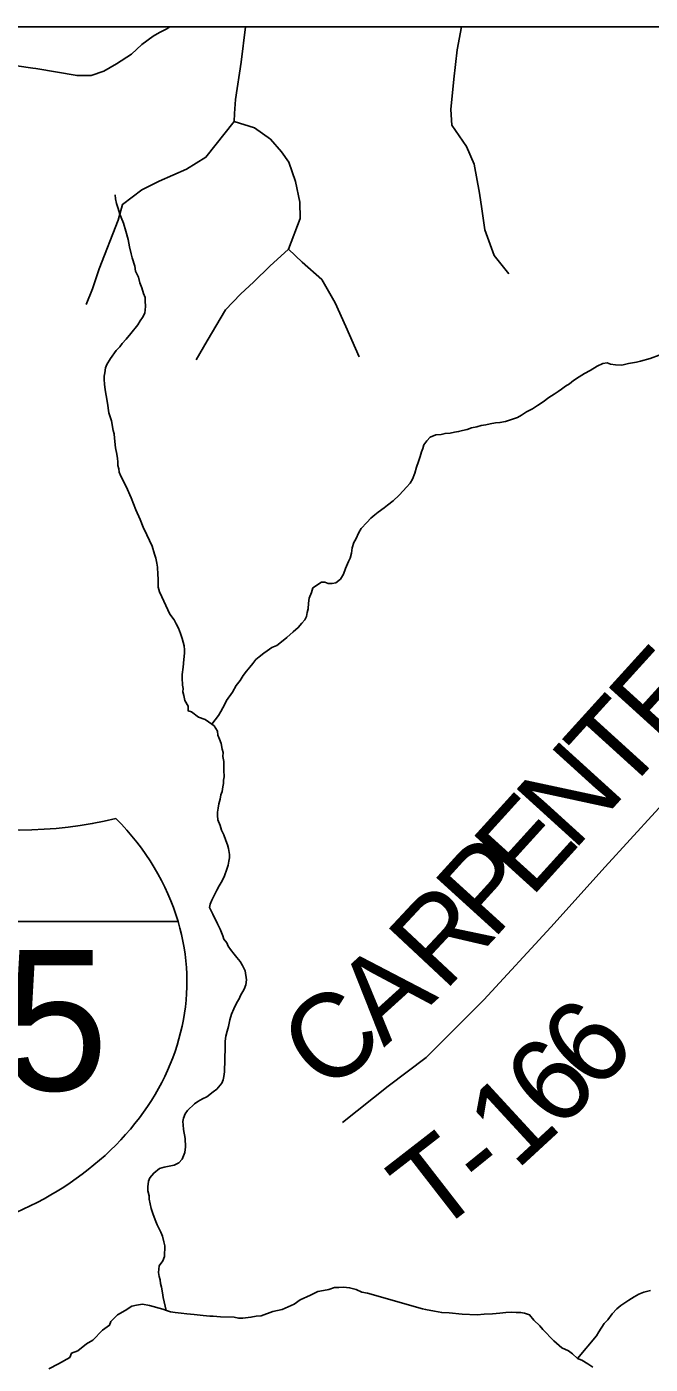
# Model space of a CAD drawing. Extents: x 0 to 34, y 0 to 22.
# Drawn here: x 7.1167 to 7.327, y 20.4487 to 20.9 of the extents above; entities that cross this region are included whole.
import ezdxf

# ---------------------------------------------------------------- set-up
doc = ezdxf.new("R2010")
doc.units = 0
for name, color, linetype in [('GM_X_Corporation', 7, 'Continuous'), ('GM_X_Interstate_Shield', 7, 'Continuous'), ('GM_X_Minor_River', 7, 'Continuous'), ('GM_X_Township_Road', 7, 'Continuous'), ('GM_X_Township_Road_Text', 7, 'Continuous'), ('SH_Cut_Line', 7, 'Continuous'), ('SH_Data', 7, 'Continuous')]:
    doc.layers.add(name, color=color, linetype=linetype)

msp = doc.modelspace()

# ---------------------------------------------------------------- linework, layer by layer
at = {"layer": 'GM_X_Corporation'}
msp.add_lwpolyline([(8.26616, 20.9), (5.67696, 20.9)], dxfattribs=at)
at = {"layer": 'GM_X_Interstate_Shield'}
msp.add_line((7.16774, 20.59808), (6.99605, 20.59808), dxfattribs=at)
msp.add_line((7.16774, 20.59808), (6.99605, 20.59808), dxfattribs=at)
for centre, start_param, end_param in [((7.11432, 20.71775), 4.415841, 5.008937), ((7.0597, 20.57779), 0.230566, 0.669003), ((7.0597, 20.57779), 4.913747, 6.513751)]:
    msp.add_ellipse(centre, major_axis=(0.11097, 0), ratio=0.8, start_param=start_param, end_param=end_param, dxfattribs=at)
at = {"layer": 'GM_X_Minor_River'}
for points in [[(7.15307, 20.8192), (7.15219, 20.82206), (7.15185, 20.8234), (7.15134, 20.82569), (7.15083, 20.82817), (7.15014, 20.83103), (7.14926, 20.83371), (7.14855, 20.83563), (7.14801, 20.83678), (7.14749, 20.83869), (7.14696, 20.84041), (7.14662, 20.84194), (7.14646, 20.84327)], [(7.18105, 20.63504), (7.18127, 20.63636), (7.1815, 20.63787), (7.18192, 20.63938), (7.18215, 20.64089), (7.18256, 20.64202), (7.18278, 20.64353), (7.183, 20.64466), (7.18303, 20.6458), (7.18325, 20.64693), (7.18312, 20.64921), (7.18319, 20.65206), (7.18285, 20.65377), (7.18289, 20.6551), (7.18254, 20.65625), (7.18221, 20.65815), (7.18168, 20.65968), (7.18114, 20.66102), (7.18098, 20.66236), (7.17989, 20.66409), (7.17802, 20.66547), (7.17691, 20.66626), (7.17465, 20.66707), (7.17222, 20.66884), (7.17109, 20.66925), (7.17113, 20.67077), (7.17004, 20.6727), (7.16971, 20.67441), (7.16936, 20.67556), (7.16938, 20.6767), (7.16922, 20.67784), (7.1691, 20.68031), (7.16913, 20.68144), (7.16938, 20.6839), (7.16963, 20.68655), (7.16988, 20.68863), (7.16991, 20.68977), (7.16975, 20.6911), (7.16905, 20.69359), (7.16853, 20.69531), (7.16781, 20.69703), (7.16709, 20.69857), (7.16637, 20.69992), (7.1649, 20.70185), (7.16219, 20.70761), (7.16148, 20.70934), (7.16095, 20.71087), (7.16102, 20.71371), (7.16087, 20.71524), (7.16074, 20.7177), (7.16059, 20.71904), (7.16025, 20.72075), (7.15971, 20.72209), (7.15902, 20.72477), (7.15722, 20.72861), (7.15596, 20.73111), (7.15488, 20.73379), (7.15345, 20.73705), (7.15184, 20.74108), (7.15023, 20.74491), (7.14842, 20.74838), (7.14788, 20.74972), (7.14772, 20.75086), (7.14737, 20.75201), (7.1474, 20.75315), (7.14724, 20.75429), (7.14709, 20.75581), (7.14657, 20.75791), (7.14627, 20.76114), (7.14612, 20.76266), (7.14577, 20.76381), (7.14529, 20.76705), (7.1444, 20.76973), (7.14392, 20.77296), (7.14341, 20.77563), (7.14308, 20.77754), (7.14294, 20.77944), (7.14279, 20.78096), (7.14282, 20.7821), (7.14304, 20.78323), (7.14327, 20.78493), (7.14368, 20.78606), (7.14487, 20.78811), (7.14684, 20.79072), (7.14801, 20.79201), (7.1488, 20.79313), (7.15016, 20.79461), (7.15173, 20.79647), (7.15409, 20.79944), (7.15488, 20.80075), (7.15567, 20.80187), (7.15646, 20.80336), (7.15671, 20.80563), (7.15657, 20.80753), (7.1566, 20.80867), (7.15606, 20.81001), (7.15554, 20.81192), (7.15483, 20.81365), (7.15431, 20.81556), (7.1534, 20.81748), (7.15307, 20.8192)], [(7.3031, 20.78188), (7.30483, 20.78298), (7.30676, 20.78406), (7.30908, 20.78552), (7.311, 20.78642), (7.31252, 20.78657), (7.31365, 20.78616), (7.31535, 20.78593), (7.31744, 20.78587), (7.31973, 20.78638), (7.32241, 20.78688), (7.32374, 20.78722), (7.32699, 20.78809), (7.33006, 20.78915)], [(7.17911, 20.66466), (7.18131, 20.66766), (7.1821, 20.66897), (7.18349, 20.67139), (7.1841, 20.67271), (7.18607, 20.6755), (7.18726, 20.67775), (7.18863, 20.67942), (7.18963, 20.6811), (7.1908, 20.68258), (7.19198, 20.68388), (7.19296, 20.68518), (7.19394, 20.68649), (7.1951, 20.6874), (7.19666, 20.68869), (7.19781, 20.68942), (7.19936, 20.69052), (7.20109, 20.69123), (7.20264, 20.69252), (7.20439, 20.69399), (7.20652, 20.69583), (7.20827, 20.6973), (7.20945, 20.69879), (7.21043, 20.6999), (7.21102, 20.70102), (7.21125, 20.70234), (7.21166, 20.70366), (7.21171, 20.70556), (7.21194, 20.70726), (7.21275, 20.70913), (7.21317, 20.71064), (7.21607, 20.71265), (7.21721, 20.71262), (7.21833, 20.71221), (7.21966, 20.71218), (7.221, 20.71233), (7.22255, 20.71362), (7.22354, 20.7153), (7.22416, 20.71718), (7.22517, 20.71962), (7.22577, 20.72074), (7.22619, 20.72244), (7.22643, 20.72414), (7.22704, 20.72602), (7.22764, 20.72714), (7.22865, 20.72939), (7.22944, 20.7307), (7.23139, 20.73274), (7.23276, 20.73422), (7.23411, 20.73532), (7.23528, 20.73624), (7.23721, 20.7377), (7.23838, 20.73862), (7.24031, 20.74009), (7.24226, 20.74194), (7.24363, 20.74342), (7.2448, 20.74471), (7.24597, 20.74601), (7.24677, 20.74732), (7.24758, 20.74938), (7.2482, 20.75145), (7.24882, 20.75334), (7.24943, 20.75503), (7.24985, 20.75653), (7.25026, 20.75766), (7.25067, 20.75898), (7.25165, 20.76028), (7.25282, 20.76158), (7.25474, 20.76228), (7.25645, 20.76243), (7.25779, 20.76277), (7.2595, 20.76292), (7.26103, 20.76326), (7.26237, 20.76341), (7.2637, 20.76376), (7.26523, 20.7641), (7.26677, 20.76463), (7.26848, 20.76496), (7.27002, 20.76549), (7.27154, 20.76564), (7.27307, 20.76598), (7.27478, 20.76631), (7.27631, 20.76646), (7.27822, 20.76679), (7.2809, 20.76767), (7.28224, 20.7682), (7.28359, 20.76893), (7.28532, 20.77002), (7.28725, 20.77111), (7.28899, 20.7722), (7.29092, 20.77348), (7.29286, 20.77494), (7.29459, 20.77604), (7.29595, 20.77695), (7.2971, 20.77768), (7.29846, 20.77878), (7.29981, 20.7795), (7.30117, 20.78061), (7.3031, 20.78188)], [(7.16374, 20.4669), (7.16264, 20.47126), (7.16249, 20.47278), (7.16216, 20.47469), (7.16181, 20.47603), (7.16165, 20.47717), (7.1613, 20.47831), (7.16115, 20.47965), (7.16118, 20.48078), (7.16139, 20.48192), (7.16258, 20.48359), (7.16318, 20.48509), (7.16327, 20.4887), (7.16293, 20.49003), (7.16241, 20.49194), (7.16187, 20.49328), (7.16061, 20.49578), (7.16026, 20.49693), (7.15936, 20.49923), (7.15866, 20.50133), (7.15798, 20.50439), (7.15801, 20.50552), (7.15748, 20.50724), (7.15751, 20.50857), (7.15775, 20.51046), (7.15816, 20.51159), (7.15953, 20.51326), (7.16147, 20.51473), (7.163, 20.51526), (7.16472, 20.51559), (7.16644, 20.51593), (7.16797, 20.51664), (7.16915, 20.51794), (7.16996, 20.5202), (7.1702, 20.52209), (7.17008, 20.52493), (7.16959, 20.52798), (7.16944, 20.5295), (7.16928, 20.53065), (7.1695, 20.53178), (7.17011, 20.53328), (7.17089, 20.5344), (7.17323, 20.53661), (7.17439, 20.53734), (7.17593, 20.53825), (7.17747, 20.53897), (7.1796, 20.54062), (7.18076, 20.54154), (7.18252, 20.54358), (7.18293, 20.5447), (7.18315, 20.54584), (7.18338, 20.54735), (7.18359, 20.55569), (7.18364, 20.55777), (7.18388, 20.55947), (7.1843, 20.56117), (7.18472, 20.56268), (7.18515, 20.56494), (7.18577, 20.56682), (7.18658, 20.5687), (7.18758, 20.57076), (7.18837, 20.57206), (7.18878, 20.57319), (7.18997, 20.57525), (7.19058, 20.57675), (7.19081, 20.57845), (7.19032, 20.5815), (7.18942, 20.58323), (7.18869, 20.58457), (7.18759, 20.58593), (7.18667, 20.58709), (7.18538, 20.58865), (7.18465, 20.5898), (7.18411, 20.59095), (7.18319, 20.59212), (7.18284, 20.59326), (7.18194, 20.59556), (7.18104, 20.59729), (7.17941, 20.60056), (7.17833, 20.60287), (7.17855, 20.604), (7.17915, 20.60531), (7.17976, 20.60662), (7.18076, 20.60868), (7.18156, 20.61018), (7.18255, 20.61186), (7.18335, 20.61355), (7.18417, 20.6158), (7.18458, 20.61712), (7.18481, 20.61844), (7.18502, 20.61957), (7.18505, 20.62071), (7.18473, 20.6228), (7.18438, 20.62395), (7.18384, 20.62548), (7.18313, 20.6274), (7.18241, 20.62893), (7.18188, 20.63047), (7.18117, 20.63238), (7.18102, 20.6339), (7.18105, 20.63504)], [(7.12405, 20.44724), (7.12732, 20.44886), (7.13117, 20.45103), (7.13178, 20.45253), (7.13389, 20.45324), (7.1368, 20.45563), (7.13892, 20.4569), (7.14223, 20.46023), (7.14455, 20.46187), (7.14497, 20.46319), (7.1473, 20.4654), (7.14981, 20.46686), (7.15212, 20.46831), (7.15365, 20.46865), (7.15575, 20.46898), (7.15802, 20.46854), (7.16254, 20.46728), (7.16386, 20.46687), (7.16518, 20.46645), (7.16669, 20.46622), (7.16877, 20.46598), (7.17067, 20.46574), (7.17313, 20.46549), (7.17616, 20.46522), (7.17843, 20.46497), (7.17957, 20.46494), (7.18204, 20.46468), (7.18659, 20.46457), (7.1881, 20.46434), (7.18962, 20.4643), (7.19229, 20.46461), (7.19401, 20.46494), (7.19572, 20.46508), (7.19974, 20.4665), (7.2028, 20.46718), (7.20491, 20.46807), (7.20683, 20.46897), (7.20896, 20.47043), (7.21242, 20.47204), (7.21492, 20.47331), (7.21683, 20.47364), (7.21854, 20.47397), (7.22046, 20.47468), (7.22198, 20.47464), (7.2235, 20.47479), (7.22559, 20.47455), (7.22785, 20.47392), (7.22973, 20.47311), (7.23161, 20.47268), (7.25018, 20.46744)], [(7.30246, 20.45072), (7.30892, 20.45833), (7.30972, 20.45963), (7.3115, 20.46243), (7.31267, 20.46373), (7.31424, 20.46577), (7.3158, 20.46744), (7.31716, 20.46854), (7.31986, 20.47037), (7.3216, 20.47146), (7.32314, 20.47237), (7.32487, 20.47308), (7.32716, 20.47359)], [(7.25018, 20.46744), (7.25123, 20.46724), (7.25425, 20.46659), (7.25671, 20.46614), (7.25917, 20.46608), (7.26353, 20.46559), (7.26865, 20.46545), (7.27094, 20.46558), (7.27379, 20.4657), (7.27626, 20.46601), (7.27836, 20.46615), (7.28007, 20.46629), (7.28178, 20.46625), (7.28329, 20.46621), (7.28462, 20.46598)], [(7.28462, 20.46598), (7.28631, 20.46537), (7.28779, 20.46362), (7.28983, 20.46167), (7.29075, 20.46051), (7.29445, 20.45662), (7.29724, 20.45427), (7.29949, 20.45326), (7.30079, 20.45228), (7.30246, 20.45072), (7.30397, 20.45011), (7.30602, 20.44892), (7.3077, 20.44774)]]:
    msp.add_lwpolyline(points, dxfattribs=at)
at = {"layer": 'GM_X_Township_Road'}
msp.add_line((7.26183, 20.89218), (7.2633, 20.9), dxfattribs=at)
for points in [[(7.03337, 20.9), (7.09081, 20.89005), (7.11874, 20.88604)], [(7.11874, 20.88604), (7.1197, 20.8859), (7.13365, 20.88352), (7.13842, 20.88352), (7.14269, 20.88502), (7.14696, 20.88754), (7.15195, 20.89079), (7.15546, 20.89401), (7.15931, 20.89679), (7.16142, 20.89807), (7.16391, 20.89935), (7.16495, 20.9)], [(7.19046, 20.9), (7.18905, 20.888), (7.18708, 20.87549), (7.18678, 20.87075), (7.18664, 20.86807), (7.17712, 20.85599), (7.17052, 20.85196), (7.16137, 20.84793), (7.15551, 20.845), (7.14891, 20.84005), (7.14754, 20.83471), (7.14112, 20.81832), (7.13882, 20.81161), (7.13669, 20.80625)], [(7.27931, 20.81661), (7.27437, 20.82284), (7.27125, 20.83145), (7.27016, 20.83859), (7.26942, 20.8439), (7.26759, 20.85361), (7.26503, 20.85965), (7.26008, 20.86679), (7.25972, 20.8721), (7.26073, 20.88232), (7.26183, 20.89218)], [(7.18664, 20.86807), (7.19351, 20.86588), (7.19891, 20.86203), (7.20266, 20.85782), (7.20505, 20.85434), (7.20734, 20.84774), (7.2088, 20.84078), (7.20889, 20.83529), (7.20495, 20.82494), (7.19873, 20.81917), (7.19333, 20.81395), (7.18875, 20.80974), (7.18371, 20.80452), (7.17754, 20.794), (7.1738, 20.78761)], [(7.20495, 20.82494), (7.20953, 20.82055), (7.21622, 20.81469), (7.22071, 20.8069), (7.22437, 20.79884), (7.22877, 20.78868)], [(7.2232, 20.53032), (7.23859, 20.54254), (7.25142, 20.55219), (7.27084, 20.57169), (7.29347, 20.59621), (7.31178, 20.61651), (7.3287, 20.63496), (7.34523, 20.65284), (7.36129, 20.67093), (7.3634, 20.6733)]]:
    msp.add_lwpolyline(points, dxfattribs=at)
at = {"layer": 'SH_Cut_Line'}
msp.add_lwpolyline([(8.9, 20.9), (5.67696, 20.9)], dxfattribs=at)
at = {"layer": 'SH_Data'}
msp.add_line((2.1, 20.9), (8.9, 20.9), dxfattribs=at)

# ---------------------------------------------------------------- texts
at = {"layer": 'GM_X_Interstate_Shield'}
msp.add_text('275', height=0.047349, dxfattribs=at).set_placement((7.0385, 20.54111))
at = {"layer": 'GM_X_Township_Road_Text'}
for s, rotation, p in [('E', 47.7678, (7.33202, 20.65565)), ('T', 47.7678, (7.31773, 20.63992)), ('N', 47.7675, (7.30093, 20.62141)), ('E', 47.7735, (7.28665, 20.60567)), ('P', 47.7302, (7.27374, 20.59147)), ('R', 46.9383, (7.25752, 20.57411)), ('A', 42.1832, (7.23716, 20.55551)), ('C', 37.9003, (7.21697, 20.53969)), ('6', 46.9399, (7.30854, 20.53988)), ('6', 45.6517, (7.29583, 20.52686)), ('1', 42.6515, (7.2818, 20.51388)), ('T', 37.8145, (7.25395, 20.49182)), ('-', 39.0019, (7.27124, 20.50525))]:
    msp.add_text(s, height=0.02841, rotation=rotation, dxfattribs=at).set_placement(p)

doc.saveas('drawing.dxf')
